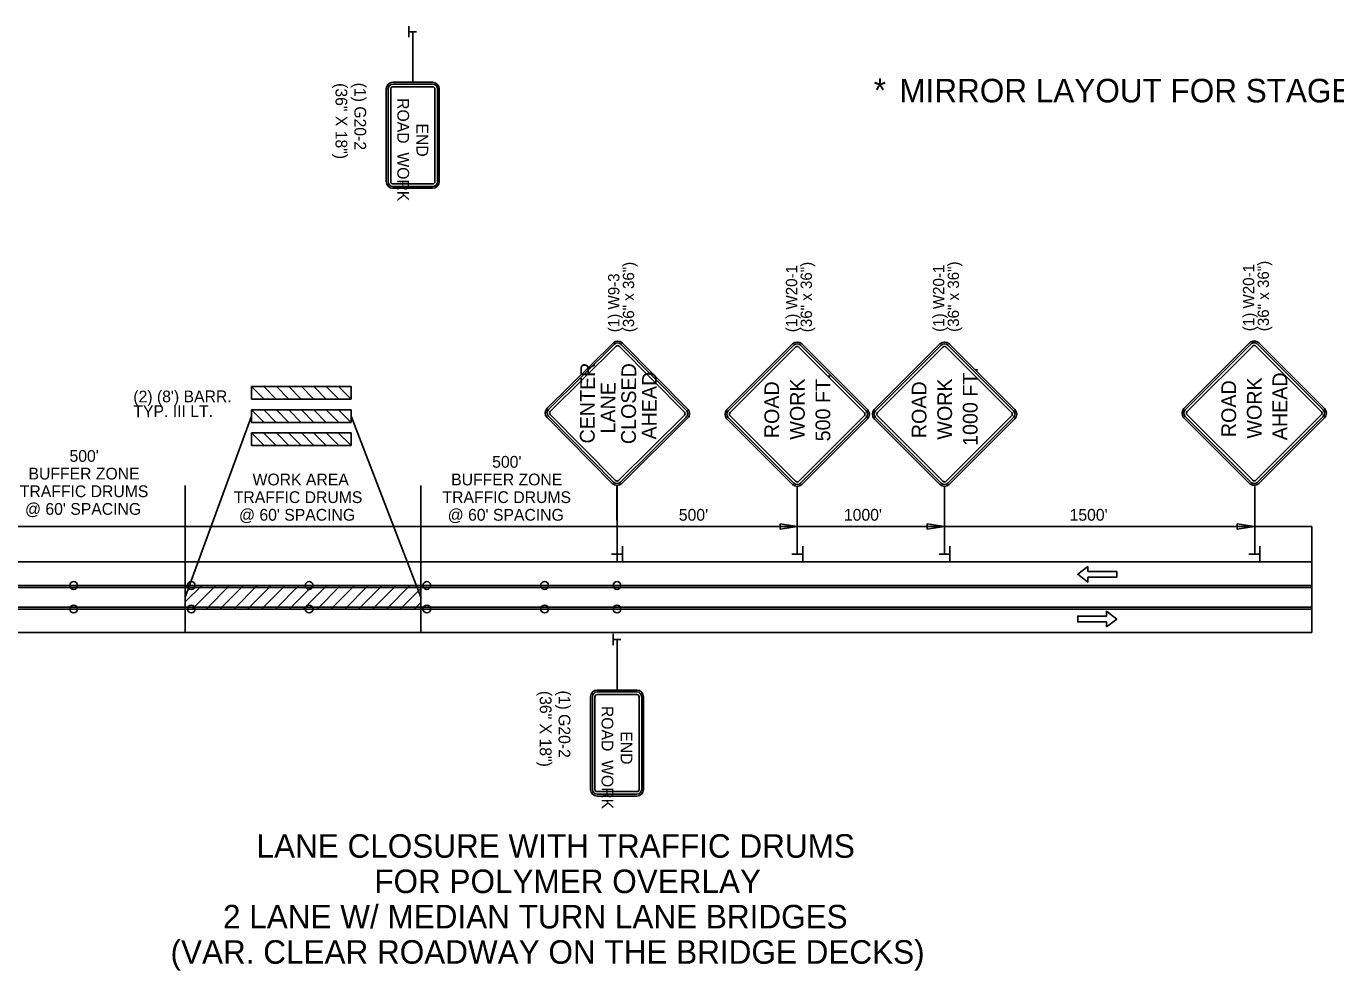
# Model space of a CAD drawing. Extents: x 1930579 to 1946213, y 596452 to 597784.
# Drawn here: x 1936788 to 1937455, y 596609 to 597090 of the extents above; entities that cross this region are included whole.
import ezdxf

# ---------------------------------------------------------------- set-up
doc = ezdxf.new("R2010")
doc.units = 0
for name, color, linetype in [('Default', 7, 'Continuous'), ('Level 3', 7, 'Continuous'), ('P_TC_Signs_Temporary', 7, 'Continuous'), ('R_Border', 7, 'Continuous'), ('R_Striping', 7, 'Continuous')]:
    doc.layers.add(name, color=color, linetype=linetype)

# ---------------------------------------------------------------- blocks, each defined once
blk = doc.blocks.new('W20-1')
at = {"layer": 'P_TC_Signs_Temporary'}
for p, q in [((-5.97, 6.53), (-0.4, 12.1)), ((-5.86, 6.42), (-0.29, 11.99)), ((-5.7, 6.26), (-0.13, 11.83)), ((0.13, 11.83), (5.7, 6.26)), ((0.29, 11.99), (5.86, 6.42)), ((0.4, 12.1), (5.97, 6.53)), ((-0.4, 0.16), (-5.97, 5.73)), ((-0.29, 0.28), (-5.86, 5.84)), ((-0.13, 0.43), (-5.7, 6)), ((5.7, 6), (0.13, 0.43)), ((5.86, 5.84), (0.29, 0.28)), ((5.97, 5.73), (0.4, 0.16))]:
    blk.add_line(p, q, dxfattribs=at)
for centre, radius, start, end in [((0, 11.7), 0.562, 45, 135), ((0, 11.7), 0.406, 45, 135), ((0, 11.7), 0.188, 45, 135), ((-5.57, 6.13), 0.562, 135, 225), ((-5.57, 6.13), 0.406, 135, 225), ((-5.57, 6.13), 0.187, 135, 225), ((5.57, 6.13), 0.187, 315, 45), ((5.57, 6.13), 0.406, 315, 45), ((5.57, 6.13), 0.562, 315, 45), ((0, 0.56), 0.562, 225, 315), ((0, 0.56), 0.406, 225, 315), ((0, 0.56), 0.188, 225, 315)]:
    blk.add_arc(centre, radius, start, end, dxfattribs=at)
for s, p in [(' ROAD ', (-2.5, 7.67)), ('WORK', (-2.16, 5.5)), (' AHEAD ', (-2.76, 3.33))]:
    blk.add_text(s, height=1.25, dxfattribs=at).set_placement(p)

msp = doc.modelspace()

# ---------------------------------------------------------------- linework, layer by layer
at = {"layer": 'Default'}
for p, q in [((1936982.52, 597084.66), (1936982.52, 597090.29)), ((1936982.6, 597087.46), (1936986.45, 597087.46)), ((1936868.61, 596781.24), (1936868.61, 596856.24)), ((1936988.61, 596781.24), (1936988.61, 596856.24)), ((1937088.61, 596817.24), (1937088.61, 596856.24)), ((1937171.76, 596833.94), (1937171.76, 596836.6)), ((1937171.76, 596836.6), (1937180.62, 596835.27)), ((1937246.71, 596833.94), (1937246.71, 596836.6)), ((1937246.71, 596836.6), (1937255.58, 596835.27)), ((1937404.65, 596833.94), (1937404.65, 596836.6)), ((1937404.65, 596836.6), (1937413.51, 596835.27)), ((1936768.61, 596835.27), (1936868.61, 596835.27)), ((1936868.61, 596835.27), (1937088.61, 596835.27)), ((1937442.72, 596835.27), (1937088.61, 596835.27)), ((1937180.62, 596835.27), (1937171.76, 596833.94)), ((1937255.58, 596835.27), (1937246.71, 596833.94)), ((1937413.51, 596835.27), (1937404.65, 596833.94)), ((1937442.72, 596835.27), (1937442.72, 596781.24)), ((1937091.45, 596825.22), (1937091.45, 596817.24)), ((1937183.34, 596825.22), (1937183.34, 596817.24)), ((1937258.29, 596825.22), (1937258.29, 596817.24)), ((1937416.23, 596825.22), (1937416.23, 596817.24)), ((1936768.61, 596817.24), (1936868.61, 596817.24)), ((1936868.61, 596817.24), (1937442.72, 596817.24)), ((1937091.34, 596821.25), (1937085.89, 596821.25)), ((1937183.22, 596821.25), (1937177.77, 596821.25)), ((1937258.18, 596821.25), (1937252.73, 596821.25)), ((1937416.11, 596821.25), (1937410.66, 596821.25)), ((1936768.61, 596805.24), (1936868.61, 596805.24)), ((1936768.61, 596804.24), (1936868.61, 596804.24)), ((1936868.61, 596805.24), (1937442.72, 596805.24)), ((1936868.61, 596803.91), (1936869.95, 596805.24)), ((1936868.61, 596796.84), (1936877.02, 596805.24)), ((1936868.61, 596804.24), (1937442.72, 596804.24)), ((1936872.09, 596793.24), (1936884.09, 596805.24)), ((1936879.16, 596793.24), (1936891.16, 596805.24)), ((1936886.23, 596793.24), (1936898.23, 596805.24)), ((1936893.3, 596793.24), (1936905.3, 596805.24)), ((1936900.37, 596793.24), (1936912.37, 596805.24)), ((1936907.44, 596793.24), (1936919.44, 596805.24)), ((1936914.51, 596793.24), (1936926.51, 596805.24)), ((1936921.58, 596793.24), (1936933.58, 596805.24)), ((1936928.66, 596793.24), (1936940.66, 596805.24)), ((1936935.73, 596793.24), (1936947.73, 596805.24)), ((1936942.8, 596793.24), (1936954.8, 596805.24)), ((1936949.87, 596793.24), (1936961.87, 596805.24)), ((1936956.94, 596793.24), (1936968.94, 596805.24)), ((1936964.01, 596793.24), (1936975.72, 596804.95)), ((1936971.08, 596793.24), (1936983.08, 596805.24)), ((1936978.15, 596793.24), (1936988.61, 596803.7)), ((1936985.22, 596793.24), (1936988.61, 596796.63)), ((1936768.61, 596794.24), (1936868.61, 596794.24)), ((1936768.61, 596793.24), (1936868.61, 596793.24)), ((1936868.61, 596794.24), (1937442.72, 596794.24)), ((1936868.61, 596793.24), (1937442.72, 596793.24)), ((1936768.61, 596781.24), (1936868.61, 596781.24)), ((1936868.61, 596781.24), (1937442.72, 596781.24)), ((1937086.61, 596774.91), (1937086.61, 596780.54)), ((1937086.69, 596777.71), (1937090.54, 596777.71))]:
    msp.add_line(p, q, dxfattribs=at)
for centre in [(1936811.71, 596805.24), (1936871.71, 596805.24), (1936931.71, 596805.24), (1936991.71, 596805.24), (1937051.71, 596805.24), (1937088.61, 596805.24), (1936811.71, 596793.24), (1936871.71, 596793.24), (1936931.71, 596793.24), (1936991.71, 596793.24), (1937051.71, 596793.24), (1937088.61, 596793.24)]:
    msp.add_circle(centre, 1.99, dxfattribs=at)
at = {"layer": 'Level 3'}
for p, q in [((1936953.21, 596906.6), (1936902.36, 596906.6)), ((1936902.36, 596900.21), (1936902.36, 596906.6)), ((1936953.21, 596900.21), (1936953.21, 596906.6)), ((1936902.4, 596900.23), (1936902.36, 596900.27)), ((1936953.21, 596900.21), (1936902.36, 596900.21)), ((1936953.21, 596894.76), (1936902.36, 596894.76)), ((1936902.36, 596888.4), (1936902.36, 596894.76)), ((1936902.36, 596888.4), (1936902.36, 596894.76)), ((1936953.21, 596888.4), (1936953.21, 596894.76)), ((1936953.21, 596888.4), (1936902.36, 596888.4)), ((1936953.21, 596882.97), (1936902.36, 596882.97)), ((1936902.36, 596876.6), (1936902.36, 596882.97)), ((1936953.21, 596876.6), (1936953.21, 596882.97)), ((1936953.21, 596876.6), (1936902.36, 596876.6))]:
    msp.add_line(p, q, dxfattribs=at)
for points in [[(1936902.36, 596906.6), (1936908.62, 596906.58), (1936914.96, 596900.23), (1936908.73, 596900.23)], [(1936915.07, 596906.6), (1936921.32, 596906.58), (1936927.67, 596900.23), (1936921.44, 596900.23)], [(1936927.78, 596906.6), (1936934.03, 596906.58), (1936940.37, 596900.23), (1936934.14, 596900.23)], [(1936940.48, 596906.6), (1936946.73, 596906.58), (1936953.08, 596900.23), (1936946.85, 596900.23)], [(1936902.36, 596894.76), (1936908.62, 596894.74), (1936914.96, 596888.4), (1936908.73, 596888.4)], [(1936915.07, 596894.76), (1936921.32, 596894.74), (1936927.67, 596888.4), (1936921.44, 596888.4)], [(1936927.78, 596894.76), (1936934.03, 596894.74), (1936940.37, 596888.4), (1936934.14, 596888.4)], [(1936940.48, 596894.76), (1936946.73, 596894.74), (1936953.08, 596888.4), (1936946.85, 596888.4)], [(1936902.36, 596882.97), (1936908.62, 596882.95), (1936914.96, 596876.6), (1936908.73, 596876.6)], [(1936915.07, 596882.97), (1936921.32, 596882.95), (1936927.67, 596876.6), (1936921.44, 596876.6)], [(1936927.78, 596882.97), (1936934.03, 596882.95), (1936940.37, 596876.6), (1936934.14, 596876.6)], [(1936940.48, 596882.97), (1936946.73, 596882.95), (1936953.08, 596876.6), (1936946.85, 596876.6)]]:
    msp.add_lwpolyline(points, close=True, dxfattribs=at)
at = {"layer": 'P_TC_Signs_Temporary'}
for p, q in [((1936971.02, 597058.31), (1936971.02, 597011.06)), ((1936971.96, 597058.31), (1936971.96, 597011.06)), ((1936973.27, 597058.31), (1936973.27, 597011.06)), ((1936994.65, 597061.68), (1936974.4, 597061.68)), ((1936994.65, 597060.75), (1936974.4, 597060.75)), ((1936994.65, 597059.43), (1936974.4, 597059.43)), ((1936995.77, 597011.06), (1936995.77, 597058.31)), ((1936997.09, 597011.06), (1936997.09, 597058.31)), ((1936998.02, 597011.06), (1936998.02, 597058.31)), ((1936974.4, 597009.93), (1936994.65, 597009.93)), ((1936974.4, 597008.62), (1936994.65, 597008.62)), ((1936974.4, 597007.68), (1936994.65, 597007.68)), ((1937053.02, 596895.59), (1937086.6, 596928.83)), ((1937053.68, 596894.93), (1937087.26, 596928.17)), ((1937054.6, 596893.99), (1937088.18, 596927.23)), ((1937089.77, 596927.23), (1937123.01, 596893.65)), ((1937090.7, 596928.15), (1937123.94, 596894.57)), ((1937091.37, 596928.81), (1937124.61, 596895.23)), ((1937144.65, 596894.94), (1937178.06, 596928.35)), ((1937145.31, 596894.28), (1937178.72, 596927.69)), ((1937146.24, 596893.35), (1937179.65, 596926.76)), ((1937181.24, 596926.76), (1937214.65, 596893.35)), ((1937182.17, 596927.69), (1937215.58, 596894.28)), ((1937182.83, 596928.35), (1937216.24, 596894.94)), ((1937219.73, 596894.94), (1937253.14, 596928.35)), ((1937220.39, 596894.28), (1937253.8, 596927.69)), ((1937221.32, 596893.35), (1937254.73, 596926.76)), ((1937256.32, 596926.76), (1937289.73, 596893.35)), ((1937257.25, 596927.69), (1937290.66, 596894.28)), ((1937257.91, 596928.35), (1937291.33, 596894.94)), ((1937086.23, 596857.24), (1937052.99, 596890.82)), ((1937086.9, 596857.9), (1937053.66, 596891.48)), ((1937087.83, 596858.82), (1937054.59, 596892.4)), ((1937123, 596892.05), (1937089.42, 596858.81)), ((1937123.93, 596891.12), (1937090.35, 596857.88)), ((1937124.59, 596890.46), (1937091.01, 596857.21)), ((1937178.06, 596856.75), (1937144.65, 596890.17)), ((1937178.72, 596857.42), (1937145.31, 596890.83)), ((1937179.65, 596858.35), (1937146.24, 596891.76)), ((1937214.65, 596891.76), (1937181.24, 596858.35)), ((1937215.58, 596890.83), (1937182.17, 596857.42)), ((1937216.24, 596890.17), (1937182.83, 596856.75)), ((1937253.14, 596856.75), (1937219.73, 596890.17)), ((1937253.8, 596857.42), (1937220.39, 596890.83)), ((1937254.73, 596858.35), (1937221.32, 596891.76)), ((1937289.73, 596891.76), (1937256.32, 596858.35)), ((1937290.66, 596890.83), (1937257.25, 596857.42)), ((1937291.33, 596890.17), (1937257.91, 596856.75)), ((1937098.74, 596751.93), (1937078.49, 596751.93)), ((1937098.74, 596751), (1937078.49, 596751)), ((1937098.74, 596749.68), (1937078.49, 596749.68)), ((1937075.11, 596748.56), (1937075.11, 596701.31)), ((1937076.05, 596748.56), (1937076.05, 596701.31)), ((1937077.36, 596748.56), (1937077.36, 596701.31)), ((1937099.86, 596701.31), (1937099.86, 596748.56)), ((1937101.18, 596701.31), (1937101.18, 596748.56)), ((1937102.11, 596701.31), (1937102.11, 596748.56)), ((1937078.49, 596700.18), (1937098.74, 596700.18)), ((1937078.49, 596698.87), (1937098.74, 596698.87)), ((1937078.49, 596697.93), (1937098.74, 596697.93))]:
    msp.add_line(p, q, dxfattribs=at)
for centre, radius, start, end in [((1936974.4, 597058.31), 3.37, 90, 180), ((1936974.4, 597058.31), 2.44, 90, 180), ((1936974.4, 597058.31), 1.13, 90, 180), ((1936994.65, 597058.31), 3.37, 360, 90), ((1936994.65, 597058.31), 2.44, 360, 90), ((1936994.65, 597058.31), 1.13, 360, 90), ((1936974.4, 597011.06), 3.37, 180, 270), ((1936974.4, 597011.06), 2.44, 180, 270), ((1936974.4, 597011.06), 1.13, 180, 270), ((1936994.65, 597011.06), 2.44, 270, 360), ((1936994.65, 597011.06), 1.13, 270, 360), ((1936994.65, 597011.06), 3.37, 270, 360), ((1937088.97, 596926.43), 3.38, 44.70829, 134.70829), ((1937180.45, 596925.96), 3.38, 45, 135), ((1937255.53, 596925.96), 3.38, 45, 135), ((1937088.97, 596926.43), 2.44, 44.70829, 134.70829), ((1937088.97, 596926.43), 1.12, 44.70829, 134.70829), ((1937180.45, 596925.96), 2.44, 45, 135), ((1937180.45, 596925.96), 1.12, 45, 135), ((1937255.53, 596925.96), 2.44, 45, 135), ((1937255.53, 596925.96), 1.12, 45, 135), ((1937055.39, 596893.19), 3.38, 134.70829, 224.70829), ((1937055.39, 596893.19), 2.44, 134.70829, 224.70829), ((1937055.39, 596893.19), 1.13, 134.70829, 224.70829), ((1937122.21, 596892.85), 1.13, 314.70829, 44.70829), ((1937122.21, 596892.85), 2.44, 314.70829, 44.70829), ((1937122.21, 596892.85), 3.38, 314.70829, 44.70829), ((1937147.04, 596892.55), 3.38, 135, 225), ((1937147.04, 596892.55), 2.44, 135, 225), ((1937147.04, 596892.55), 1.13, 135, 225), ((1937213.86, 596892.55), 1.13, 315, 45), ((1937213.86, 596892.55), 2.44, 315, 45), ((1937213.86, 596892.55), 3.38, 315, 45), ((1937222.12, 596892.55), 3.38, 135, 225), ((1937222.12, 596892.55), 2.44, 135, 225), ((1937222.12, 596892.55), 1.13, 135, 225), ((1937288.94, 596892.55), 1.13, 315, 45), ((1937288.94, 596892.55), 2.44, 315, 45), ((1937288.94, 596892.55), 3.38, 315, 45), ((1937088.63, 596859.61), 3.38, 224.70829, 314.70829), ((1937088.63, 596859.61), 2.44, 224.70829, 314.70829), ((1937088.63, 596859.61), 1.12, 224.70829, 314.70829), ((1937180.45, 596859.14), 3.38, 225, 315), ((1937180.45, 596859.14), 2.44, 225, 315), ((1937180.45, 596859.14), 1.12, 225, 315), ((1937255.53, 596859.14), 3.38, 225, 315), ((1937255.53, 596859.14), 2.44, 225, 315), ((1937255.53, 596859.14), 1.12, 225, 315), ((1937078.49, 596748.56), 3.37, 90, 180), ((1937078.49, 596748.56), 2.44, 90, 180), ((1937078.49, 596748.56), 1.13, 90, 180), ((1937098.74, 596748.56), 3.37, 360, 90), ((1937098.74, 596748.56), 2.44, 360, 90), ((1937098.74, 596748.56), 1.13, 360, 90), ((1937078.49, 596701.31), 3.37, 180, 270), ((1937078.49, 596701.31), 2.44, 180, 270), ((1937078.49, 596701.31), 1.13, 180, 270), ((1937098.74, 596701.31), 2.44, 270, 360), ((1937098.74, 596701.31), 1.13, 270, 360), ((1937098.74, 596701.31), 3.37, 270, 360)]:
    msp.add_arc(centre, radius, start, end, dxfattribs=at)
at = {"layer": 'R_Border'}
for p, q in [((1936984.52, 597061.68), (1936984.52, 597087.46)), ((1936868.61, 596799.24), (1936902.36, 596891.58)), ((1936988.61, 596799.24), (1936953.21, 596891.58)), ((1937088.61, 596821.25), (1937088.56, 596855.77)), ((1937180.5, 596821.25), (1937180.45, 596855.77)), ((1937255.58, 596821.25), (1937255.53, 596855.77)), ((1937413.64, 596821.25), (1937413.59, 596855.77)), ((1937088.61, 596751.93), (1937088.61, 596777.71))]:
    msp.add_line(p, q, dxfattribs=at)
at = {"layer": 'R_Striping'}
for points in [[(1937328.58, 596814.96), (1937323.39, 596810.96), (1937328.58, 596806.96), (1937328.58, 596809.46), (1937343.3, 596809.46), (1937343.3, 596812.46), (1937328.58, 596812.46)], [(1937338.1, 596784.15), (1937343.3, 596788.15), (1937338.1, 596792.15), (1937338.1, 596789.65), (1937323.39, 596789.65), (1937323.39, 596786.65), (1937338.1, 596786.65)]]:
    msp.add_lwpolyline(points, close=True, dxfattribs=at)

# ---------------------------------------------------------------- block references
at = {"layer": 'Default', "xscale": 6, "yscale": 6, "rotation": 89.99999999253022}
msp.add_blockref('W20-1', (1937450.12, 596893.06), dxfattribs=at)

# ---------------------------------------------------------------- texts
at = {"layer": 'Default'}
for s, height, p in [('*', 12, (1937219.48, 597051.68)), ('MIRROR LAYOUT FOR STAGE 3', 12, (1937232.5, 597051.46)), ("500'", 6, (1936809.59, 596868.27)), ("500' ", 6, (1937024.99, 596865.27)), ('BUFFER ZONE', 6, (1936788.71, 596859.27)), ('TRAFFIC DRUMS ', 6, (1936784.27, 596850.27)), ('WORK AREA', 6, (1936902.89, 596856.27)), ('BUFFER ZONE', 6, (1937004.11, 596856.27)), ('TRAFFIC DRUMS ', 6, (1936893.32, 596847.27)), ('TRAFFIC DRUMS ', 6, (1936999.66, 596847.27)), ("@ 60' SPACING", 6, (1936786.94, 596841.27)), ("@ 60' SPACING", 6, (1936895.99, 596838.27)), ("@ 60' SPACING", 6, (1937002.33, 596838.27)), ('LANE CLOSURE WITH TRAFFIC DRUMS', 12, (1936904.92, 596666.49)), ('FOR POLYMER OVERLAY', 12, (1936964.92, 596648.49)), ('2 LANE W/ MEDIAN TURN LANE BRIDGES', 12, (1936887.82, 596630.49)), ('(VAR. CLEAR ROADWAY ON THE BRIDGE DECKS)', 12, (1936861.08, 596612.49))]:
    msp.add_text(s, height=height, dxfattribs=at).set_placement(p)
for s, p in [("500'", (1937120.11, 596838.27)), ("1000'", (1937204.25, 596838.27)), ("1500'", (1937319.24, 596838.27))]:
    msp.add_text(s, height=6, rotation=360, dxfattribs=at).set_placement(p)
at = {"layer": 'P_TC_Signs_Temporary'}
for s, height, rotation, p in [('ROAD  WORK', 6, 270, (1936976.65, 597053.64)), ('END', 6, 270, (1936986.4, 597040.71)), ('CENTER', 7.5, 89.70829, (1937077.2, 596877.6)), ('CLOSED', 7.5, 89.70829, (1937098.2, 596877.29)), ('AHEAD', 7.5, 89.70829, (1937108.71, 596879.63)), ('WORK', 7.5, 90, (1937184.26, 596879.56)), ('500 FT.', 7.5, 90, (1937197.28, 596878.71)), ('WORK', 7.5, 90, (1937259.34, 596879.56)), ('1000 FT.', 7.5, 90, (1937272.36, 596876.38)), ('LANE', 7.5, 89.70829, (1937087.73, 596882.69)), (' ROAD ', 7.5, 90, (1937171.23, 596877.53)), (' ROAD ', 7.5, 90, (1937246.32, 596877.53)), ('ROAD  WORK', 6, 270, (1937080.74, 596743.89)), ('END', 6, 270, (1937090.49, 596730.96))]:
    msp.add_text(s, height=height, rotation=rotation, dxfattribs=at).set_placement(p)
at = {"layer": 'R_Border'}
for s, height, rotation, p in [('(36" X 18")', 6, 270, (1936945.16, 597061.27)), ('(1) G20-2', 6, 270, (1936954.75, 597061.49)), ('(36" x 36")', 5.76, 90, (1937097.33, 596934.34)), ('(36" x 36")', 5.76, 90, (1937187.94, 596934.34)), ('(36" x 36")', 5.76, 90, (1937262.89, 596934.52)), ('(36" x 36")', 5.76, 90, (1937420.83, 596934.85)), ('(1) W9-3', 5.76, 90, (1937089.84, 596934.34)), ('(1) W20-1', 5.76, 90, (1937180.45, 596934.34)), ('(1) W20-1', 5.76, 90, (1937255.4, 596934.52)), ('(1) W20-1', 5.76, 90, (1937413.34, 596934.85)), ("(2) (8') BARR.", 6, 0.17192, (1936842.13, 596898.52)), ('TYP. III LT.', 6, 0.17192, (1936842.15, 596891.01)), ('(36" X 18")', 6, 270, (1937049.25, 596751.52)), ('(1) G20-2', 6, 270, (1937058.84, 596751.74))]:
    msp.add_text(s, height=height, rotation=rotation, dxfattribs=at).set_placement(p)

doc.saveas('drawing.dxf')
